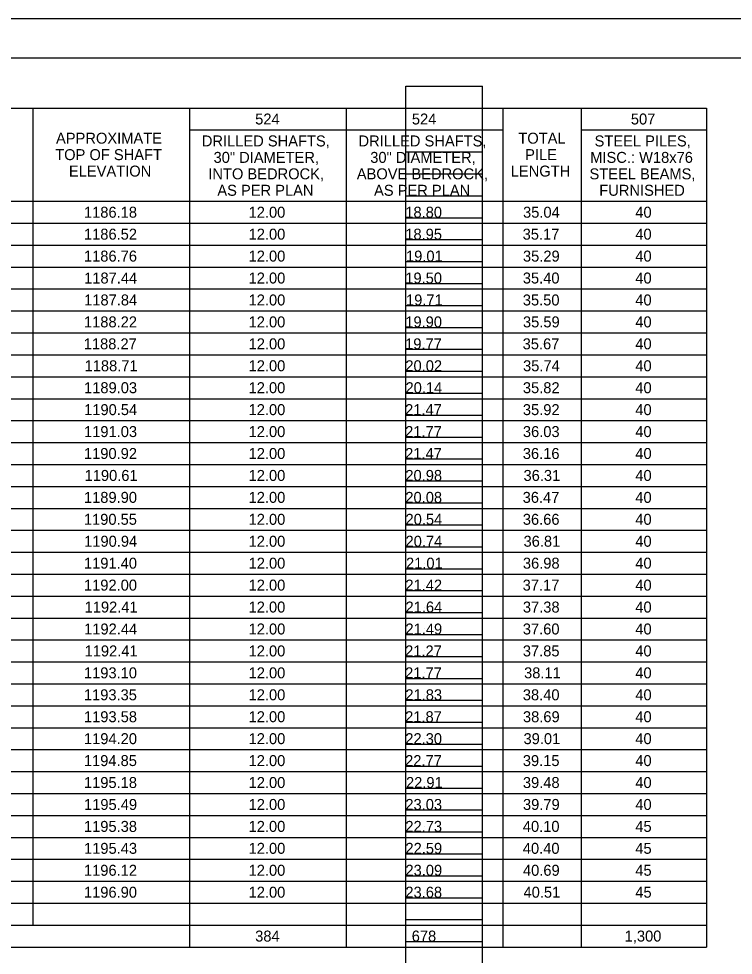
# Model space of a CAD drawing. Extents: x 0 to 34, y 0 to 22.
# Drawn here: x 11.32 to 20.44, y 10.04 to 22 of the extents above; entities that cross this region are included whole.
import ezdxf

# ---------------------------------------------------------------- set-up
doc = ezdxf.new("R2010")
doc.units = 0
for name, color, linetype in [('RD_P_Text', 7, 'Continuous'), ('SC_Scratch1', 7, 'Continuous'), ('SC_Scratch2', 7, 'Continuous'), ('SH_Border', 7, 'Continuous'), ('SH_Cut_Line', 7, 'Continuous')]:
    doc.layers.add(name, color=color, linetype=linetype)

msp = doc.modelspace()

# ---------------------------------------------------------------- linework, layer by layer
at = {"layer": 'RD_P_Text'}
for p, q in [((2.4, 20.86), (20.1, 20.86)), ((11.5, 20.86), (11.5, 10.43)), ((13.5, 20.86), (13.5, 10.15)), ((15.5, 20.86), (15.5, 10.15)), ((17.5, 20.86), (17.5, 10.15)), ((18.5, 20.86), (18.5, 10.15)), ((20.1, 20.86), (20.1, 10.15)), ((13.5, 20.58), (17.5, 20.58)), ((18.5, 20.58), (20.1, 20.58)), ((2.4, 19.67), (20.1, 19.67)), ((2.4, 19.39), (20.1, 19.39)), ((2.4, 19.11), (20.1, 19.11)), ((2.4, 18.83), (20.1, 18.83)), ((2.4, 18.55), (20.1, 18.55)), ((2.4, 18.27), (20.1, 18.27)), ((2.4, 17.99), (20.1, 17.99)), ((2.4, 17.71), (20.1, 17.71)), ((2.4, 17.43), (20.1, 17.43)), ((2.4, 17.15), (20.1, 17.15)), ((2.4, 16.87), (20.1, 16.87)), ((2.4, 16.59), (20.1, 16.59)), ((2.4, 16.31), (20.1, 16.31)), ((2.4, 16.03), (20.1, 16.03)), ((2.4, 15.75), (20.1, 15.75)), ((2.4, 15.47), (20.1, 15.47)), ((2.4, 15.19), (20.1, 15.19)), ((2.4, 14.91), (20.1, 14.91)), ((2.4, 14.63), (20.1, 14.63)), ((2.4, 14.35), (20.1, 14.35)), ((2.4, 14.07), (20.1, 14.07)), ((2.4, 13.79), (20.1, 13.79)), ((2.4, 13.51), (20.1, 13.51)), ((2.4, 13.23), (20.1, 13.23)), ((2.4, 12.95), (20.1, 12.95)), ((2.4, 12.67), (20.1, 12.67)), ((2.4, 12.39), (20.1, 12.39)), ((2.4, 12.11), (20.1, 12.11)), ((2.4, 11.83), (20.1, 11.83)), ((2.4, 11.55), (20.1, 11.55)), ((2.4, 11.27), (20.1, 11.27)), ((2.4, 10.99), (20.1, 10.99)), ((2.4, 10.71), (20.1, 10.71)), ((2.4, 10.43), (20.1, 10.43)), ((2.4, 10.15), (20.1, 10.15))]:
    msp.add_line(p, q, dxfattribs=at)
at = {"layer": 'SC_Scratch1'}
for p, q in [((12.5, 19.53), (12.5, 19.53)), ((14.5, 19.53), (14.5, 19.53)), ((16.5, 19.53), (16.5, 19.53)), ((18, 19.53), (18, 19.53)), ((19.3, 19.53), (19.3, 19.53)), ((12.5, 19.25), (12.5, 19.25)), ((14.5, 19.25), (14.5, 19.25)), ((16.5, 19.25), (16.5, 19.25)), ((18, 19.25), (18, 19.25)), ((19.3, 19.25), (19.3, 19.25)), ((12.5, 18.97), (12.5, 18.97)), ((14.5, 18.97), (14.5, 18.97)), ((16.5, 18.97), (16.5, 18.97)), ((18, 18.97), (18, 18.97)), ((19.3, 18.97), (19.3, 18.97)), ((12.5, 18.69), (12.5, 18.69)), ((14.5, 18.69), (14.5, 18.69)), ((16.5, 18.69), (16.5, 18.69)), ((18, 18.69), (18, 18.69)), ((19.3, 18.69), (19.3, 18.69)), ((12.5, 18.41), (12.5, 18.41)), ((14.5, 18.41), (14.5, 18.41)), ((16.5, 18.41), (16.5, 18.41)), ((18, 18.41), (18, 18.41)), ((19.3, 18.41), (19.3, 18.41)), ((12.5, 18.13), (12.5, 18.13)), ((14.5, 18.13), (14.5, 18.13)), ((16.5, 18.13), (16.5, 18.13)), ((18, 18.13), (18, 18.13)), ((19.3, 18.13), (19.3, 18.13)), ((12.5, 17.85), (12.5, 17.85)), ((14.5, 17.85), (14.5, 17.85)), ((16.5, 17.85), (16.5, 17.85)), ((18, 17.85), (18, 17.85)), ((19.3, 17.85), (19.3, 17.85)), ((12.5, 17.57), (12.5, 17.57)), ((14.5, 17.57), (14.5, 17.57)), ((16.5, 17.57), (16.5, 17.57)), ((18, 17.57), (18, 17.57)), ((19.3, 17.57), (19.3, 17.57)), ((12.5, 17.29), (12.5, 17.29)), ((14.5, 17.29), (14.5, 17.29)), ((16.5, 17.29), (16.5, 17.29)), ((18, 17.29), (18, 17.29)), ((19.3, 17.29), (19.3, 17.29)), ((12.5, 17.01), (12.5, 17.01)), ((14.5, 17.01), (14.5, 17.01)), ((16.5, 17.01), (16.5, 17.01)), ((18, 17.01), (18, 17.01)), ((19.3, 17.01), (19.3, 17.01)), ((12.5, 16.73), (12.5, 16.73)), ((14.5, 16.73), (14.5, 16.73)), ((16.5, 16.73), (16.5, 16.73)), ((18, 16.73), (18, 16.73)), ((19.3, 16.73), (19.3, 16.73)), ((12.5, 16.45), (12.5, 16.45)), ((14.5, 16.45), (14.5, 16.45)), ((16.5, 16.45), (16.5, 16.45)), ((18, 16.45), (18, 16.45)), ((19.3, 16.45), (19.3, 16.45)), ((12.5, 16.17), (12.5, 16.17)), ((14.5, 16.17), (14.5, 16.17)), ((16.5, 16.17), (16.5, 16.17)), ((18, 16.17), (18, 16.17)), ((19.3, 16.17), (19.3, 16.17)), ((12.5, 15.89), (12.5, 15.89)), ((14.5, 15.89), (14.5, 15.89)), ((16.5, 15.89), (16.5, 15.89)), ((18, 15.89), (18, 15.89)), ((19.3, 15.89), (19.3, 15.89)), ((12.5, 15.61), (12.5, 15.61)), ((14.5, 15.61), (14.5, 15.61)), ((16.5, 15.61), (16.5, 15.61)), ((18, 15.61), (18, 15.61)), ((19.3, 15.61), (19.3, 15.61)), ((12.5, 15.33), (12.5, 15.33)), ((14.5, 15.33), (14.5, 15.33)), ((16.5, 15.33), (16.5, 15.33)), ((18, 15.33), (18, 15.33)), ((19.3, 15.33), (19.3, 15.33)), ((12.5, 15.05), (12.5, 15.05)), ((14.5, 15.05), (14.5, 15.05)), ((16.5, 15.05), (16.5, 15.05)), ((18, 15.05), (18, 15.05)), ((19.3, 15.05), (19.3, 15.05)), ((12.5, 14.77), (12.5, 14.77)), ((14.5, 14.77), (14.5, 14.77)), ((16.5, 14.77), (16.5, 14.77)), ((18, 14.77), (18, 14.77)), ((19.3, 14.77), (19.3, 14.77)), ((12.5, 14.49), (12.5, 14.49)), ((14.5, 14.49), (14.5, 14.49)), ((16.5, 14.49), (16.5, 14.49)), ((18, 14.49), (18, 14.49)), ((19.3, 14.49), (19.3, 14.49)), ((12.5, 14.21), (12.5, 14.21)), ((14.5, 14.21), (14.5, 14.21)), ((16.5, 14.21), (16.5, 14.21)), ((18, 14.21), (18, 14.21)), ((19.3, 14.21), (19.3, 14.21)), ((12.5, 13.93), (12.5, 13.93)), ((14.5, 13.93), (14.5, 13.93)), ((16.5, 13.93), (16.5, 13.93)), ((18, 13.93), (18, 13.93)), ((19.3, 13.93), (19.3, 13.93)), ((12.5, 13.65), (12.5, 13.65)), ((14.5, 13.65), (14.5, 13.65)), ((16.5, 13.65), (16.5, 13.65)), ((18, 13.65), (18, 13.65)), ((19.3, 13.65), (19.3, 13.65)), ((12.5, 13.37), (12.5, 13.37)), ((14.5, 13.37), (14.5, 13.37)), ((16.5, 13.37), (16.5, 13.37)), ((18, 13.37), (18, 13.37)), ((19.3, 13.37), (19.3, 13.37)), ((12.5, 13.09), (12.5, 13.09)), ((14.5, 13.09), (14.5, 13.09)), ((16.5, 13.09), (16.5, 13.09)), ((18, 13.09), (18, 13.09)), ((19.3, 13.09), (19.3, 13.09)), ((12.5, 12.81), (12.5, 12.81)), ((14.5, 12.81), (14.5, 12.81)), ((16.5, 12.81), (16.5, 12.81)), ((18, 12.81), (18, 12.81)), ((19.3, 12.81), (19.3, 12.81)), ((12.5, 12.53), (12.5, 12.53)), ((14.5, 12.53), (14.5, 12.53)), ((16.5, 12.53), (16.5, 12.53)), ((18, 12.53), (18, 12.53)), ((19.3, 12.53), (19.3, 12.53)), ((12.5, 12.25), (12.5, 12.25)), ((14.5, 12.25), (14.5, 12.25)), ((16.5, 12.25), (16.5, 12.25)), ((18, 12.25), (18, 12.25)), ((19.3, 12.25), (19.3, 12.25)), ((12.5, 11.97), (12.5, 11.97)), ((14.5, 11.97), (14.5, 11.97)), ((16.5, 11.97), (16.5, 11.97)), ((18, 11.97), (18, 11.97)), ((19.3, 11.97), (19.3, 11.97)), ((12.5, 11.69), (12.5, 11.69)), ((14.5, 11.69), (14.5, 11.69)), ((16.5, 11.69), (16.5, 11.69)), ((18, 11.69), (18, 11.69)), ((19.3, 11.69), (19.3, 11.69)), ((12.5, 11.41), (12.5, 11.41)), ((14.5, 11.41), (14.5, 11.41)), ((16.5, 11.41), (16.5, 11.41)), ((18, 11.41), (18, 11.41)), ((19.3, 11.41), (19.3, 11.41)), ((12.5, 11.13), (12.5, 11.13)), ((14.5, 11.13), (14.5, 11.13)), ((16.5, 11.13), (16.5, 11.13)), ((18, 11.13), (18, 11.13)), ((19.3, 11.13), (19.3, 11.13)), ((12.5, 10.85), (12.5, 10.85)), ((14.5, 10.85), (14.5, 10.85)), ((16.5, 10.85), (16.5, 10.85)), ((18, 10.85), (18, 10.85)), ((19.3, 10.85), (19.3, 10.85)), ((14.5, 10.29), (14.5, 10.29)), ((16.5, 10.29), (16.5, 10.29)), ((19.3, 10.29), (19.3, 10.29))]:
    msp.add_line(p, q, dxfattribs=at)
at = {"layer": 'SC_Scratch2'}
for p, q in [((16.26, 0.98), (16.26, 21.14)), ((16.26, 21.14), (17.24, 21.14)), ((17.24, 0.98), (17.24, 21.14)), ((16.26, 20.86), (17.24, 20.86)), ((16.26, 20.58), (17.24, 20.58)), ((16.26, 20.3), (17.24, 20.3)), ((16.26, 20.02), (17.24, 20.02)), ((16.26, 19.74), (17.24, 19.74)), ((16.26, 19.46), (17.24, 19.46)), ((16.26, 19.18), (17.24, 19.18)), ((16.26, 18.9), (17.24, 18.9)), ((16.26, 18.62), (17.24, 18.62)), ((16.26, 18.34), (17.24, 18.34)), ((16.26, 18.06), (17.24, 18.06)), ((16.26, 17.78), (17.24, 17.78)), ((16.26, 17.5), (17.24, 17.5)), ((16.26, 17.22), (17.24, 17.22)), ((16.26, 16.94), (17.24, 16.94)), ((16.26, 16.66), (17.24, 16.66)), ((16.26, 16.38), (17.24, 16.38)), ((16.26, 16.1), (17.24, 16.1)), ((16.26, 15.82), (17.24, 15.82)), ((16.26, 15.54), (17.24, 15.54)), ((16.26, 15.26), (17.24, 15.26)), ((16.26, 14.98), (17.24, 14.98)), ((16.26, 14.7), (17.24, 14.7)), ((16.26, 14.42), (17.24, 14.42)), ((16.26, 14.14), (17.24, 14.14)), ((16.26, 13.86), (17.24, 13.86)), ((16.26, 13.58), (17.24, 13.58)), ((16.26, 13.3), (17.24, 13.3)), ((16.26, 13.02), (17.24, 13.02)), ((16.26, 12.74), (17.24, 12.74)), ((16.26, 12.46), (17.24, 12.46)), ((16.26, 12.18), (17.24, 12.18)), ((16.26, 11.9), (17.24, 11.9)), ((16.26, 11.62), (17.24, 11.62)), ((16.26, 11.34), (17.24, 11.34)), ((16.26, 11.06), (17.24, 11.06)), ((16.26, 10.78), (17.24, 10.78)), ((16.26, 10.5), (17.24, 10.5)), ((16.26, 10.22), (17.24, 10.22))]:
    msp.add_line(p, q, dxfattribs=at)
at = {"layer": 'SH_Border'}
msp.add_lwpolyline([(1.5, 21.5), (33.5, 21.5), (33.5, 0.5), (1.5, 0.5)], close=True, dxfattribs=at)
at = {"layer": 'SH_Cut_Line'}
msp.add_lwpolyline([(0, 0), (34, 0), (34, 22), (0, 22)], close=True, dxfattribs=at)

# ---------------------------------------------------------------- texts
at = {"layer": 'RD_P_Text'}
for s, p in [('524', (14.338, 20.65)), ('524', (16.338, 20.65)), ('507', (19.133, 20.65)), ('APPROXIMATE', (11.796, 20.405)), ('DRILLED SHAFTS,', (13.657, 20.37)), ('DRILLED SHAFTS,', (15.657, 20.37)), ('TOTAL', (17.697, 20.405)), ('STEEL PILES,', (18.67, 20.37)), ('TOP OF SHAFT', (11.786, 20.195)), ('PILE', (17.784, 20.195)), ('30" DIAMETER,', (13.807, 20.16)), ('30" DIAMETER,', (15.807, 20.16)), ('MISC.: W18x76', (18.614, 20.16)), ('ELEVATION', (11.961, 19.985)), ('INTO BEDROCK,', (13.74, 19.95)), ('ABOVE BEDROCK,', (15.635, 19.95)), ('LENGTH', (17.6, 19.985)), ('STEEL BEAMS,', (18.605, 19.95)), ('AS PER PLAN', (13.855, 19.74)), ('AS PER PLAN', (15.855, 19.74)), ('FURNISHED', (18.73, 19.74)), ('1186.18', (12.153, 19.46)), ('12.00', (14.254, 19.46)), ('18.80', (16.254, 19.46)), ('35.04', (17.757, 19.46)), ('40', (19.19, 19.46)), ('1186.52', (12.153, 19.18)), ('12.00', (14.254, 19.18)), ('18.95', (16.254, 19.18)), ('35.17', (17.752, 19.18)), ('40', (19.19, 19.18)), ('1186.76', (12.153, 18.9)), ('12.00', (14.254, 18.9)), ('19.01', (16.263, 18.9)), ('35.29', (17.756, 18.9)), ('40', (19.19, 18.9)), ('1187.44', (12.155, 18.62)), ('12.00', (14.254, 18.62)), ('19.50', (16.254, 18.62)), ('35.40', (17.754, 18.62)), ('40', (19.19, 18.62)), ('1187.84', (12.155, 18.34)), ('12.00', (14.254, 18.34)), ('19.71', (16.263, 18.34)), ('35.50', (17.754, 18.34)), ('40', (19.19, 18.34)), ('1188.22', (12.153, 18.06)), ('12.00', (14.254, 18.06)), ('19.90', (16.254, 18.06)), ('35.59', (17.756, 18.06)), ('40', (19.19, 18.06)), ('1188.27', (12.15, 17.78)), ('12.00', (14.254, 17.78)), ('19.77', (16.252, 17.78)), ('35.67', (17.752, 17.78)), ('40', (19.19, 17.78)), ('1188.71', (12.161, 17.5)), ('12.00', (14.254, 17.5)), ('20.02', (16.255, 17.5)), ('35.74', (17.757, 17.5)), ('40', (19.19, 17.5)), ('1189.03', (12.154, 17.22)), ('12.00', (14.254, 17.22)), ('20.14', (16.257, 17.22)), ('35.82', (17.755, 17.22)), ('40', (19.19, 17.22)), ('1190.54', (12.155, 16.94)), ('12.00', (14.254, 16.94)), ('21.47', (16.252, 16.94)), ('35.92', (17.755, 16.94)), ('40', (19.19, 16.94)), ('1191.03', (12.154, 16.66)), ('12.00', (14.254, 16.66)), ('21.77', (16.252, 16.66)), ('36.03', (17.755, 16.66)), ('40', (19.19, 16.66)), ('1190.92', (12.153, 16.38)), ('12.00', (14.254, 16.38)), ('21.47', (16.252, 16.38)), ('36.16', (17.754, 16.38)), ('40', (19.19, 16.38)), ('1190.61', (12.161, 16.1)), ('12.00', (14.254, 16.1)), ('20.98', (16.255, 16.1)), ('36.31', (17.763, 16.1)), ('40', (19.19, 16.1)), ('1189.90', (12.153, 15.82)), ('12.00', (14.254, 15.82)), ('20.08', (16.255, 15.82)), ('36.47', (17.752, 15.82)), ('40', (19.19, 15.82)), ('1190.55', (12.152, 15.54)), ('12.00', (14.254, 15.54)), ('20.54', (16.257, 15.54)), ('36.66', (17.754, 15.54)), ('40', (19.19, 15.54)), ('1190.94', (12.155, 15.26)), ('12.00', (14.254, 15.26)), ('20.74', (16.257, 15.26)), ('36.81', (17.763, 15.26)), ('40', (19.19, 15.26)), ('1191.40', (12.153, 14.98)), ('12.00', (14.254, 14.98)), ('21.01', (16.263, 14.98)), ('36.98', (17.755, 14.98)), ('40', (19.19, 14.98)), ('1192.00', (12.153, 14.7)), ('12.00', (14.254, 14.7)), ('21.42', (16.255, 14.7)), ('37.17', (17.752, 14.7)), ('40', (19.19, 14.7)), ('1192.41', (12.161, 14.42)), ('12.00', (14.254, 14.42)), ('21.64', (16.257, 14.42)), ('37.38', (17.755, 14.42)), ('40', (19.19, 14.42)), ('1192.44', (12.155, 14.14)), ('12.00', (14.254, 14.14)), ('21.49', (16.256, 14.14)), ('37.60', (17.754, 14.14)), ('40', (19.19, 14.14)), ('1192.41', (12.161, 13.86)), ('12.00', (14.254, 13.86)), ('21.27', (16.252, 13.86)), ('37.85', (17.754, 13.86)), ('40', (19.19, 13.86)), ('1193.10', (12.153, 13.58)), ('12.00', (14.254, 13.58)), ('21.77', (16.252, 13.58)), ('38.11', (17.77, 13.58)), ('40', (19.19, 13.58)), ('1193.35', (12.152, 13.3)), ('12.00', (14.254, 13.3)), ('21.83', (16.255, 13.3)), ('38.40', (17.754, 13.3)), ('40', (19.19, 13.3)), ('1193.58', (12.153, 13.02)), ('12.00', (14.254, 13.02)), ('21.87', (16.252, 13.02)), ('38.69', (17.756, 13.02)), ('40', (19.19, 13.02)), ('1194.20', (12.153, 12.74)), ('12.00', (14.254, 12.74)), ('22.30', (16.254, 12.74)), ('39.01', (17.763, 12.74)), ('40', (19.19, 12.74)), ('1194.85', (12.152, 12.46)), ('12.00', (14.254, 12.46)), ('22.77', (16.252, 12.46)), ('39.15', (17.754, 12.46)), ('40', (19.19, 12.46)), ('1195.18', (12.153, 12.18)), ('12.00', (14.254, 12.18)), ('22.91', (16.263, 12.18)), ('39.48', (17.755, 12.18)), ('40', (19.19, 12.18)), ('1195.49', (12.154, 11.9)), ('12.00', (14.254, 11.9)), ('23.03', (16.255, 11.9)), ('39.79', (17.756, 11.9)), ('40', (19.19, 11.9)), ('1195.38', (12.153, 11.62)), ('12.00', (14.254, 11.62)), ('22.73', (16.255, 11.62)), ('40.10', (17.754, 11.62)), ('45', (19.19, 11.62)), ('1195.43', (12.154, 11.34)), ('12.00', (14.254, 11.34)), ('22.59', (16.256, 11.34)), ('40.40', (17.754, 11.34)), ('45', (19.19, 11.34)), ('1196.12', (12.153, 11.06)), ('12.00', (14.254, 11.06)), ('23.09', (16.256, 11.06)), ('40.69', (17.756, 11.06)), ('45', (19.19, 11.06)), ('1196.90', (12.153, 10.78)), ('12.00', (14.254, 10.78)), ('23.68', (16.255, 10.78)), ('40.51', (17.763, 10.78)), ('45', (19.19, 10.78)), ('384', (14.338, 10.22)), ('678', (16.336, 10.22)), ('1,300', (19.054, 10.22))]:
    msp.add_text(s, height=0.14, dxfattribs=at).set_placement(p)

doc.saveas('drawing.dxf')
